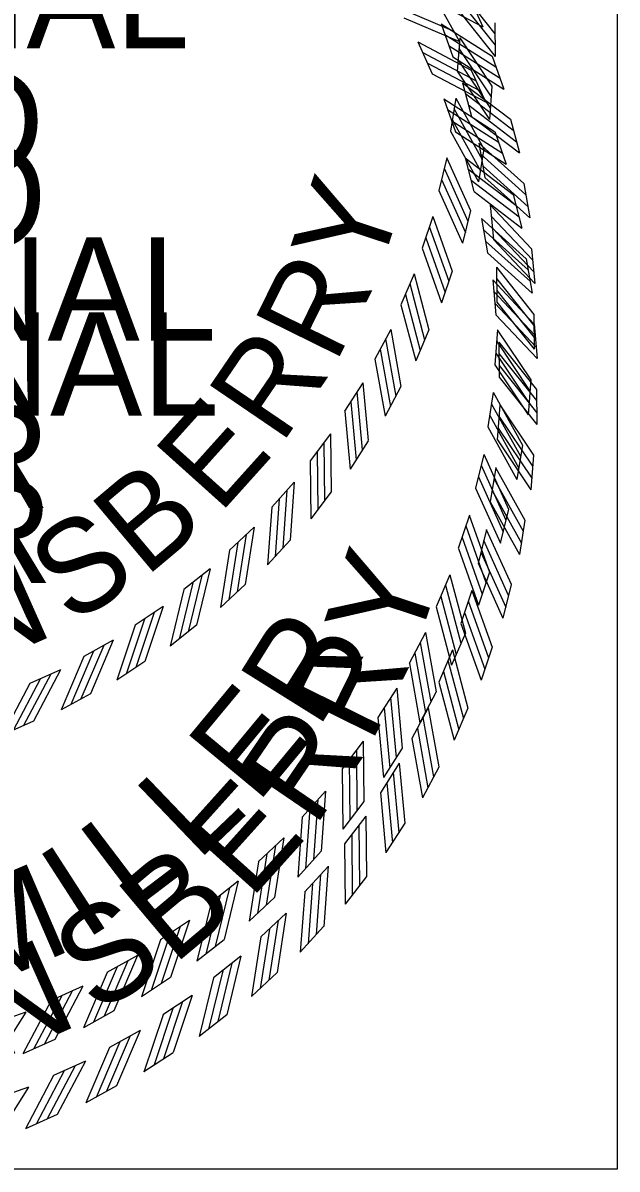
# Model space of a CAD drawing. Extents: x 0 to 1228740, y 0 to 152440.
# Drawn here: x 32.495 to 33.423, y 22.685 to 24.476 of the extents above; entities that cross this region are included whole.
import ezdxf

# ---------------------------------------------------------------- set-up
doc = ezdxf.new("R2010")
doc.units = 0
for name, color, linetype in [('R_No Plot', 7, 'Continuous'), ('STAMP_LKM', 7, 'Continuous'), ('STAMP_PP', 7, 'Continuous'), ('STAMP_SPT', 7, 'Continuous')]:
    doc.layers.add(name, color=color, linetype=linetype)

msp = doc.modelspace()

# ---------------------------------------------------------------- linework, layer by layer
at = {"layer": 'R_No Plot'}
msp.add_lwpolyline([(30.6731, 25.4352), (33.4231, 25.4352), (33.4231, 22.6852), (30.6731, 22.6852)], close=True, dxfattribs=at)
at = {"layer": 'STAMP_LKM'}
for p, q in [((33.1913, 24.5193), (33.2136, 24.4697)), ((33.1487, 24.4743), (33.1669, 24.4229)), ((33.2281, 24.4236), (33.2462, 24.3723)), ((33.1819, 24.3822), (33.1958, 24.3295)), ((33.2568, 24.3251), (33.2707, 24.2725)), ((33.2074, 24.2877), (33.2169, 24.234)), ((33.2774, 24.2247), (33.2868, 24.1711)), ((33.2251, 24.1914), (33.2301, 24.1371)), ((33.2895, 24.1228), (33.2945, 24.0686)), ((33.2347, 24.094), (33.2352, 24.0395)), ((33.2932, 24.0203), (33.2937, 23.9659)), ((33.2362, 23.9962), (33.2322, 23.9418)), ((33.2885, 23.9179), (33.2845, 23.8636)), ((33.2296, 23.8985), (33.2211, 23.8446)), ((33.2753, 23.8162), (33.2668, 23.7624)), ((33.215, 23.8017), (33.2021, 23.7488)), ((33.2537, 23.7159), (33.2408, 23.663)), ((33.1925, 23.7065), (33.1752, 23.6548)), ((33.2239, 23.6178), (33.2068, 23.5661)), ((33.1621, 23.6134), (33.1407, 23.5633)), ((33.1242, 23.5232), (33.0987, 23.475)), ((33.1862, 23.5224), (33.1648, 23.4724)), ((33.079, 23.4364), (33.0496, 23.3905)), ((33.1407, 23.4305), (33.1152, 23.3824)), ((33.0267, 23.3536), (32.9936, 23.3103)), ((33.0877, 23.3427), (33.0584, 23.2968)), ((32.9678, 23.2755), (32.9313, 23.235)), ((33.0277, 23.2595), (32.9947, 23.2163)), ((32.9027, 23.2024), (32.8629, 23.1651)), ((32.961, 23.1816), (32.9245, 23.1412)), ((32.8317, 23.135), (32.789, 23.1012)), ((32.8881, 23.1094), (32.8484, 23.0722)), ((32.7554, 23.0737), (32.71, 23.0435)), ((32.8095, 23.0435), (32.7669, 23.0097)), ((32.6743, 23.0189), (32.6266, 22.9925)), ((32.7258, 22.9844), (32.6805, 22.9542)), ((32.589, 22.971), (32.5393, 22.9486)), ((32.5, 22.9303), (32.4486, 22.9121)), ((32.6374, 22.9323), (32.5898, 22.906)), ((32.545, 22.8878), (32.4954, 22.8654))]:
    msp.add_line(p, q, dxfattribs=at)
for points in [[(33.1304, 24.5136), (33.2136, 24.4697)], [(33.1486, 24.4743), (33.228, 24.4236)], [(33.1543, 24.4578), (33.2337, 24.4071)], [(33.161, 24.4401), (33.2404, 24.3894)], [(33.1669, 24.4229), (33.2462, 24.3723)], [(33.1819, 24.3823), (33.2567, 24.3252)], [(33.1862, 24.3653), (33.261, 24.3082)], [(33.1914, 24.3471), (33.2663, 24.2901)], [(33.1958, 24.3295), (33.2707, 24.2725)], [(33.2074, 24.2878), (33.2773, 24.2247)], [(33.2103, 24.2705), (33.2802, 24.2074)], [(33.214, 24.252), (33.2839, 24.1889)], [(33.2169, 24.2341), (33.2868, 24.171)], [(33.225, 24.1915), (33.2895, 24.1229)], [(33.2264, 24.174), (33.2909, 24.1054)], [(33.2286, 24.1553), (33.2931, 24.0867)], [(33.2301, 24.1372), (33.2946, 24.0686)], [(33.2346, 24.0941), (33.2932, 24.0204)], [(33.2346, 24.0766), (33.2932, 24.0029)], [(33.2352, 24.0577), (33.2938, 23.984)], [(33.2352, 24.0396), (33.2938, 23.9659)], [(33.2361, 23.9962), (33.2884, 23.918)], [(33.2347, 23.9788), (33.287, 23.9005)], [(33.2337, 23.9599), (33.286, 23.8816)], [(33.2322, 23.9418), (33.2845, 23.8636)], [(33.2296, 23.8986), (33.2752, 23.8163)], [(33.2267, 23.8813), (33.2723, 23.799)], [(33.2242, 23.8626), (33.2698, 23.7802)], [(33.2212, 23.8447), (33.2668, 23.7624)], [(33.215, 23.8018), (33.2537, 23.716)], [(33.2107, 23.7848), (33.2494, 23.699)], [(33.2066, 23.7664), (33.2453, 23.6806)], [(33.2022, 23.7488), (33.2409, 23.663)], [(33.1868, 23.69), (33.2182, 23.6013)], [(33.1924, 23.7066), (33.2239, 23.6178)], [(33.1812, 23.6719), (33.2127, 23.5832)], [(33.1753, 23.6548), (33.2068, 23.5661)], [(33.1621, 23.6135), (33.1862, 23.5225)], [(33.1551, 23.5975), (33.1791, 23.5065)], [(33.148, 23.5799), (33.1721, 23.4889)], [(33.1408, 23.5633), (33.1648, 23.4723)], [(33.1242, 23.5233), (33.1407, 23.4306)], [(33.1159, 23.5079), (33.1323, 23.4152)], [(33.0988, 23.475), (33.1152, 23.3824)], [(33.1074, 23.491), (33.1238, 23.3983)], [(33.0694, 23.4218), (33.0781, 23.3281)], [(33.079, 23.4365), (33.0877, 23.3428)], [(33.0596, 23.4057), (33.0683, 23.312)], [(33.0497, 23.3905), (33.0584, 23.2968)], [(33.0267, 23.3537), (33.0277, 23.2596)], [(33.016, 23.3399), (33.0169, 23.2458)], [(33.0048, 23.3246), (33.0058, 23.2305)], [(32.9937, 23.3103), (32.9947, 23.2162)], [(32.956, 23.2627), (32.9492, 23.1688)], [(32.9678, 23.2756), (32.961, 23.1817)], [(32.9436, 23.2484), (32.9368, 23.1545)], [(32.9313, 23.235), (32.9245, 23.1412)], [(32.8898, 23.1907), (32.8753, 23.0977)], [(32.9027, 23.2025), (32.8881, 23.1095)], [(32.8763, 23.1774), (32.8618, 23.0844)], [(32.863, 23.1652), (32.8484, 23.0722)], [(32.8317, 23.1351), (32.8096, 23.0436)], [(32.8179, 23.1244), (32.7957, 23.0329)], [(32.7891, 23.1012), (32.7669, 23.0097)], [(32.8034, 23.1123), (32.7812, 23.0208)], [(32.7408, 23.0642), (32.7111, 22.9749)], [(32.7554, 23.0738), (32.7258, 22.9845)], [(32.7253, 23.0534), (32.6956, 22.9641)], [(32.7101, 23.0435), (32.6805, 22.9541)], [(32.659, 23.0107), (32.622, 22.9241)], [(32.6744, 23.019), (32.6374, 22.9324)], [(32.6267, 22.9925), (32.5897, 22.9059)], [(32.6426, 23.0012), (32.6057, 22.9146)], [(32.5559, 22.9559), (32.512, 22.8727)], [(32.573, 22.964), (32.529, 22.8808)], [(32.589, 22.9711), (32.5451, 22.8878)], [(32.5393, 22.9486), (32.4954, 22.8654)], [(32.5, 22.9304), (32.4493, 22.851)]]:
    msp.add_lwpolyline(points, dxfattribs=at)
at = {"layer": 'STAMP_PP'}
for p, q in [((33.2324, 24.4757), (33.2329, 24.4233)), ((33.1775, 24.4524), (33.1736, 24.4)), ((33.2278, 24.377), (33.224, 24.3247)), ((33.1711, 24.3583), (33.163, 24.3065)), ((33.1571, 24.2651), (33.1446, 24.2141)), ((33.2151, 24.279), (33.207, 24.2273)), ((33.1354, 24.1734), (33.1188, 24.1236)), ((33.1943, 24.1825), (33.1819, 24.1315)), ((33.1061, 24.0838), (33.0855, 24.0355)), ((33.1657, 24.0879), (33.1491, 24.0382)), ((33.0696, 23.9969), (33.0451, 23.9504)), ((33.1293, 23.9961), (33.1087, 23.9479)), ((33.0261, 23.9133), (32.9977, 23.869)), ((33.0855, 23.9076), (33.0609, 23.8613)), ((32.9757, 23.8336), (32.9439, 23.7918)), ((33.0345, 23.823), (33.0062, 23.7788)), ((32.919, 23.7583), (32.8838, 23.7193)), ((32.9767, 23.7429), (32.9449, 23.7012)), ((32.8562, 23.6879), (32.8179, 23.652)), ((32.9124, 23.6678), (32.8773, 23.629)), ((32.7879, 23.623), (32.7467, 23.5904)), ((32.8422, 23.5983), (32.804, 23.5625)), ((32.7144, 23.564), (32.6707, 23.5348)), ((32.7665, 23.5349), (32.7255, 23.5023)), ((32.6363, 23.5112), (32.5904, 23.4858)), ((32.6858, 23.4779), (32.6422, 23.4488)), ((32.5541, 23.465), (32.5062, 23.4435)), ((32.6007, 23.4278), (32.5549, 23.4024)), ((32.5118, 23.3848), (32.464, 23.3634))]:
    msp.add_line(p, q, dxfattribs=at)
for points in [[(33.1759, 24.5298), (33.2324, 24.4589)], [(33.1765, 24.5116), (33.2329, 24.4407)], [(33.1765, 24.4942), (33.2329, 24.4232)], [(33.1774, 24.4525), (33.2278, 24.3771)], [(33.176, 24.4357), (33.2264, 24.3603)], [(33.1751, 24.4175), (33.2254, 24.3421)], [(33.1736, 24.4001), (33.224, 24.3247)], [(33.1711, 24.3584), (33.2151, 24.2791)], [(33.1683, 24.3418), (33.2123, 24.2625)], [(33.1659, 24.3237), (33.2099, 24.2444)], [(33.163, 24.3065), (33.207, 24.2272)], [(33.157, 24.2652), (33.1943, 24.1825)], [(33.1529, 24.2489), (33.1902, 24.1662)], [(33.149, 24.2311), (33.1863, 24.1484)], [(33.1447, 24.2141), (33.182, 24.1315)], [(33.1353, 24.1735), (33.1656, 24.088)], [(33.1299, 24.1575), (33.1602, 24.0721)], [(33.1245, 24.1401), (33.1548, 24.0547)], [(33.1188, 24.1236), (33.1491, 24.0382)], [(33.1061, 24.0838), (33.1293, 23.9962)], [(33.0993, 24.0684), (33.1225, 23.9807)], [(33.0926, 24.0515), (33.1157, 23.9638)], [(33.0855, 24.0355), (33.1087, 23.9479)], [(33.0696, 23.9969), (33.0854, 23.9077)], [(33.0616, 23.9821), (33.0774, 23.8928)], [(33.0534, 23.9658), (33.0693, 23.8766)], [(33.0451, 23.9505), (33.061, 23.8612)], [(33.0261, 23.9133), (33.0345, 23.8231)], [(33.0168, 23.8992), (33.0252, 23.8089)], [(32.9978, 23.8691), (33.0062, 23.7788)], [(33.0074, 23.8837), (33.0158, 23.7934)], [(32.9757, 23.8336), (32.9767, 23.743)], [(32.9654, 23.8203), (32.9663, 23.7297)], [(32.9546, 23.8056), (32.9556, 23.7149)], [(32.9439, 23.7918), (32.9449, 23.7012)], [(32.9076, 23.7459), (32.901, 23.6555)], [(32.919, 23.7584), (32.9124, 23.6679)], [(32.8957, 23.7322), (32.8891, 23.6417)], [(32.8839, 23.7193), (32.8773, 23.6289)], [(32.8439, 23.6766), (32.8298, 23.587)], [(32.8563, 23.688), (32.8422, 23.5984)], [(32.8308, 23.6638), (32.8168, 23.5743)], [(32.818, 23.652), (32.804, 23.5624)], [(32.7879, 23.6231), (32.7666, 23.535)], [(32.7606, 23.6011), (32.7392, 23.513)], [(32.7746, 23.6127), (32.7532, 23.5246)], [(32.7468, 23.5904), (32.7255, 23.5023)], [(32.7144, 23.564), (32.6859, 23.478)], [(32.7003, 23.5548), (32.6718, 23.4688)], [(32.6708, 23.5348), (32.6422, 23.4488)], [(32.6854, 23.5444), (32.6568, 23.4583)], [(32.6363, 23.5112), (32.6008, 23.4278)], [(32.6058, 23.4941), (32.5702, 23.4107)], [(32.6215, 23.5032), (32.5859, 23.4198)], [(32.5904, 23.4858), (32.5549, 23.4024)], [(32.5387, 23.4583), (32.4964, 23.3781)], [(32.5542, 23.4651), (32.5118, 23.3849)], [(32.5063, 23.4435), (32.4639, 23.3633)], [(32.5223, 23.4505), (32.4799, 23.3703)]]:
    msp.add_lwpolyline(points, dxfattribs=at)
at = {"layer": 'STAMP_SPT'}
for p, q in [((33.1506, 24.4943), (33.177, 24.4467)), ((33.1119, 24.4459), (33.1343, 24.3962)), ((33.1952, 24.402), (33.2175, 24.3524)), ((33.1527, 24.3569), (33.1708, 24.3055)), ((33.232, 24.3062), (33.2501, 24.2549)), ((33.1859, 24.2649), (33.1997, 24.2121)), ((33.2608, 24.2078), (33.2746, 24.1552)), ((33.2114, 24.1704), (33.2208, 24.1167)), ((33.2813, 24.1073), (33.2907, 24.0537)), ((33.229, 24.0741), (33.234, 24.0198)), ((33.2935, 24.0055), (33.2984, 23.9513)), ((33.2386, 23.9767), (33.2391, 23.9222)), ((33.2972, 23.903), (33.2977, 23.8486)), ((33.2401, 23.8788), (33.2361, 23.8244)), ((33.2924, 23.8005), (33.2884, 23.7463)), ((33.2336, 23.7812), (33.2251, 23.7273)), ((33.2792, 23.6988), (33.2707, 23.6451)), ((33.219, 23.6844), (33.2061, 23.6314)), ((33.1964, 23.5892), (33.1792, 23.5374)), ((33.2576, 23.5986), (33.2448, 23.5457)), ((33.1661, 23.4961), (33.1446, 23.446)), ((33.2279, 23.5004), (33.2107, 23.4488)), ((33.1282, 23.4059), (33.1026, 23.3577)), ((33.1901, 23.4051), (33.1687, 23.355)), ((33.0829, 23.3191), (33.0535, 23.2731)), ((33.1446, 23.3132), (33.1191, 23.2651)), ((33.0307, 23.2363), (32.9976, 23.193)), ((33.0916, 23.2253), (33.0623, 23.1795)), ((32.9718, 23.1581), (32.9352, 23.1177)), ((33.0316, 23.1422), (32.9986, 23.0989)), ((32.9066, 23.0851), (32.8668, 23.0478)), ((32.9649, 23.0642), (32.9285, 23.0239)), ((32.8356, 23.0177), (32.7929, 22.9838)), ((32.8921, 22.9921), (32.8524, 22.9549)), ((32.7594, 22.9564), (32.714, 22.9261)), ((32.8135, 22.9262), (32.7708, 22.8924)), ((32.6783, 22.9016), (32.6305, 22.8752)), ((32.7297, 22.867), (32.6844, 22.8369)), ((32.5929, 22.8537), (32.5432, 22.8313)), ((32.5039, 22.813), (32.4525, 22.7948)), ((32.6413, 22.815), (32.5937, 22.7887)), ((32.5489, 22.7704), (32.4993, 22.7481))]:
    msp.add_line(p, q, dxfattribs=at)
for points in [[(33.0818, 24.4996), (33.1684, 24.4626)], [(33.0904, 24.4836), (33.177, 24.4467)], [(33.1119, 24.446), (33.1951, 24.402)], [(33.1189, 24.4299), (33.2022, 24.386)], [(33.127, 24.4129), (33.2103, 24.3689)], [(33.1343, 24.3963), (33.2176, 24.3523)], [(33.1526, 24.357), (33.2319, 24.3063)], [(33.1583, 24.3404), (33.2376, 24.2897)], [(33.165, 24.3227), (33.2443, 24.2721)], [(33.1708, 24.3056), (33.2502, 24.2549)], [(33.1858, 24.2649), (33.2607, 24.2079)], [(33.1901, 24.2479), (33.265, 24.1909)], [(33.1953, 24.2298), (33.2702, 24.1727)], [(33.1998, 24.2122), (33.2746, 24.1551)], [(33.2113, 24.1704), (33.2812, 24.1074)], [(33.2142, 24.1532), (33.2841, 24.0901)], [(33.2179, 24.1346), (33.2878, 24.0716)], [(33.2209, 24.1167), (33.2908, 24.0537)], [(33.2289, 24.0742), (33.2934, 24.0056)], [(33.2304, 24.0567), (33.2948, 23.9881)], [(33.2325, 24.0379), (33.297, 23.9693)], [(33.234, 24.0199), (33.2985, 23.9513)], [(33.2385, 23.9768), (33.2971, 23.9031)], [(33.2385, 23.9592), (33.2971, 23.8856)], [(33.2391, 23.9404), (33.2977, 23.8667)], [(33.2391, 23.9222), (33.2977, 23.8485)], [(33.2401, 23.8789), (33.2924, 23.8006)], [(33.2386, 23.8614), (33.2909, 23.7832)], [(33.2377, 23.8426), (33.2899, 23.7643)], [(33.2362, 23.8245), (33.2884, 23.7462)], [(33.2335, 23.7813), (33.2792, 23.6989)], [(33.2306, 23.764), (33.2763, 23.6816)], [(33.2281, 23.7452), (33.2738, 23.6629)], [(33.2251, 23.7274), (33.2708, 23.645)], [(33.2189, 23.6845), (33.2576, 23.5987)], [(33.2146, 23.6675), (33.2533, 23.5817)], [(33.2106, 23.649), (33.2492, 23.5632)], [(33.2061, 23.6315), (33.2448, 23.5456)], [(33.1964, 23.5892), (33.2279, 23.5005)], [(33.1907, 23.5727), (33.2222, 23.4839)], [(33.1851, 23.5546), (33.2166, 23.4659)], [(33.1792, 23.5375), (33.2107, 23.4487)], [(33.1661, 23.4962), (33.1901, 23.4052)], [(33.159, 23.4801), (33.1831, 23.3891)], [(33.152, 23.4626), (33.176, 23.3716)], [(33.1447, 23.446), (33.1687, 23.355)], [(33.1281, 23.4059), (33.1446, 23.3133)], [(33.1198, 23.3905), (33.1363, 23.2979)], [(33.1113, 23.3736), (33.1278, 23.281)], [(33.1027, 23.3577), (33.1192, 23.265)], [(33.0829, 23.3192), (33.0916, 23.2254)], [(33.0733, 23.3045), (33.0821, 23.2108)], [(33.0635, 23.2884), (33.0722, 23.1946)], [(33.0536, 23.2732), (33.0623, 23.1794)], [(33.0307, 23.2364), (33.0316, 23.1423)], [(33.0088, 23.2073), (33.0097, 23.1132)], [(33.0199, 23.2226), (33.0209, 23.1284)], [(32.9976, 23.193), (32.9986, 23.0989)], [(32.9718, 23.1582), (32.965, 23.0643)], [(32.9599, 23.1453), (32.9531, 23.0514)], [(32.9353, 23.1177), (32.9285, 23.0238)], [(32.9476, 23.131), (32.9407, 23.0371)], [(32.9066, 23.0852), (32.8921, 22.9922)], [(32.8937, 23.0733), (32.8792, 22.9803)], [(32.8669, 23.0478), (32.8524, 22.9548)], [(32.8802, 23.0601), (32.8657, 22.9671)], [(32.8357, 23.0178), (32.8135, 22.9263)], [(32.8073, 22.995), (32.7851, 22.9035)], [(32.8218, 23.007), (32.7997, 22.9155)], [(32.793, 22.9838), (32.7708, 22.8923)], [(32.7594, 22.9565), (32.7297, 22.8671)], [(32.7447, 22.9469), (32.7151, 22.8575)], [(32.7141, 22.9261), (32.6844, 22.8368)], [(32.7292, 22.9361), (32.6996, 22.8467)], [(32.6783, 22.9017), (32.6414, 22.8151)], [(32.6466, 22.8838), (32.6096, 22.7972)], [(32.6629, 22.8933), (32.626, 22.8067)], [(32.6306, 22.8752), (32.5937, 22.7886)], [(32.593, 22.8537), (32.549, 22.7705)], [(32.5433, 22.8313), (32.4993, 22.748)], [(32.5599, 22.8386), (32.5159, 22.7553)], [(32.5769, 22.8467), (32.533, 22.7635)], [(32.504, 22.813), (32.4533, 22.7337)]]:
    msp.add_lwpolyline(points, dxfattribs=at)

# ---------------------------------------------------------------- texts
at = {"layer": 'STAMP_LKM'}
for s, height, p in [('LICENSED', 0.16155, (31.4481, 24.2409)), ('PROFESSIONAL', 0.161547, (31.1173, 23.9794)), ('ENGINEER', 0.16155, (31.4096, 23.7178))]:
    msp.add_text(s, height=height, dxfattribs=at).set_placement(p)
for s, rotation, p in [('R', 57.9868, (32.9555, 23.3706)), ('E', 50.326, (32.8605, 23.2538)), ('L', 43.7596, (32.7673, 23.1645)), ('L', 37.1932, (32.6645, 23.0865)), ('I', 32.8156, (32.5913, 23.0412)), ('M', 23.3308, (32.4221, 22.9631))]:
    msp.add_text(s, height=0.1504, rotation=rotation, dxfattribs=at).set_placement(p)
at = {"layer": 'STAMP_PP'}
msp.add_text('PROFESSIONAL', height=0.155591, dxfattribs=at).set_placement((31.1367, 24.4362))
for s, rotation, p in [('Y', 71.7733, (33.0494, 24.0774)), ('R', 63.7477, (32.9831, 23.9408)), ('R', 55.7221, (32.8983, 23.8147)), ('E', 48.0613, (32.8018, 23.7066)), ('B', 40.0357, (32.6862, 23.6081)), ('S', 32.7397, (32.57, 23.5335)), ('N', 23.9845, (32.4195, 23.4642))]:
    msp.add_text(s, height=0.1448, rotation=rotation, dxfattribs=at).set_placement(p)
at = {"layer": 'STAMP_SPT'}
for s, height, p in [('LICENSED', 0.16155, (31.452, 24.1236)), ('PROFESSIONAL', 0.161547, (31.1213, 23.862)), ('ENGINEER', 0.16155, (31.4136, 23.6005))]:
    msp.add_text(s, height=height, dxfattribs=at).set_placement(p)
for s, rotation, p in [('Y', 71.7733, (33.1071, 23.4895)), ('R', 63.7477, (33.0383, 23.3476)), ('R', 55.7221, (32.9503, 23.2168)), ('E', 48.0613, (32.8501, 23.1045)), ('B', 40.0357, (32.73, 23.0023)), ('S', 32.7397, (32.6094, 22.9247)), ('N', 23.9845, (32.4532, 22.8528))]:
    msp.add_text(s, height=0.1503, rotation=rotation, dxfattribs=at).set_placement(p)

doc.saveas('drawing.dxf')
